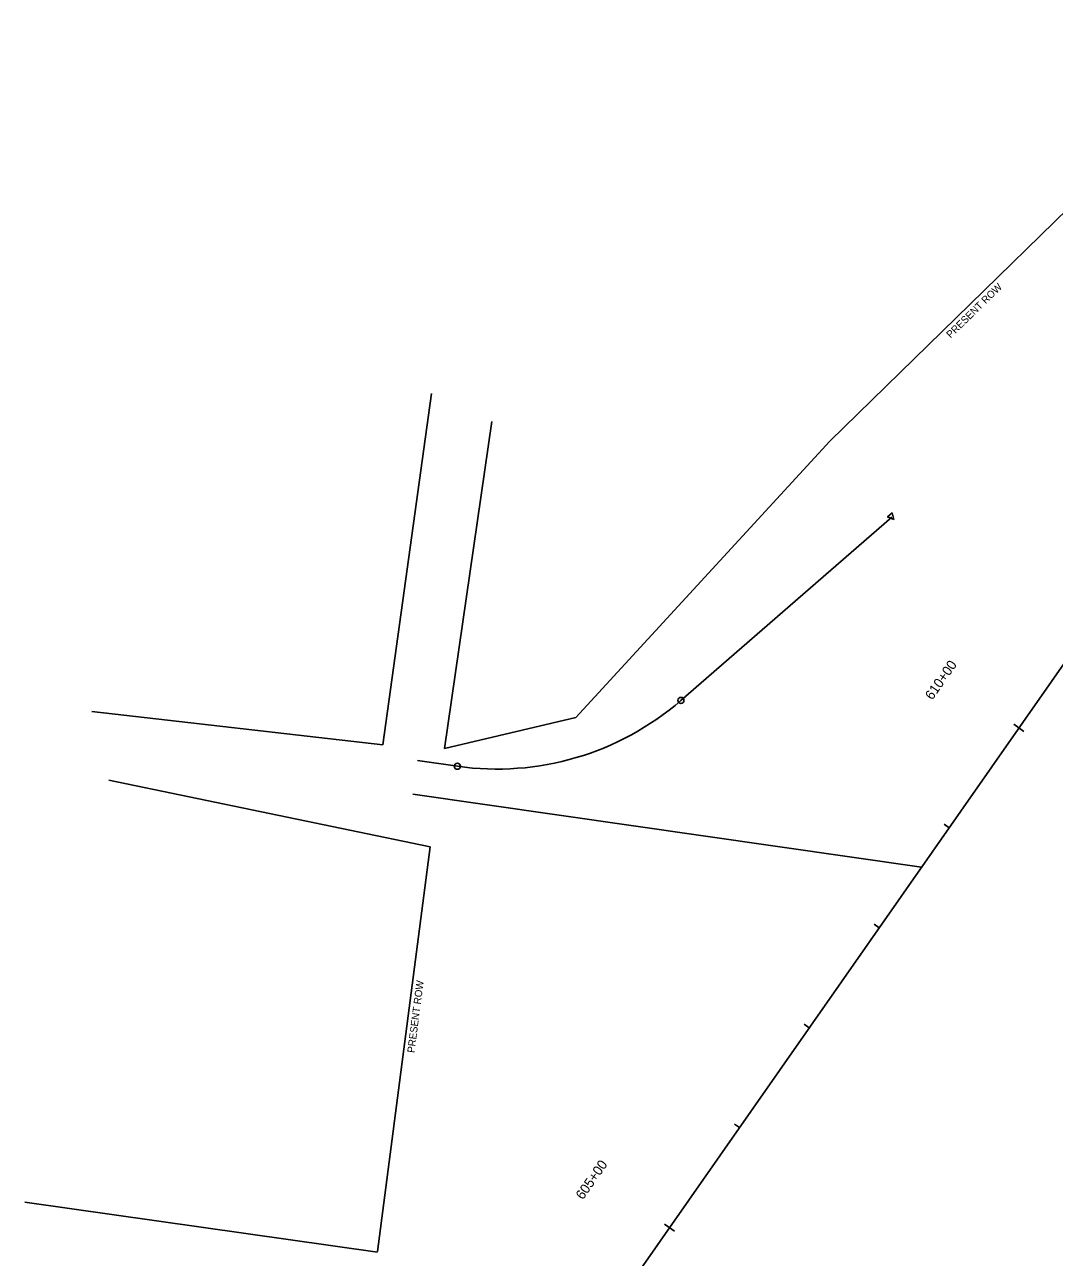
# Model space of a CAD drawing. Extents: x 1790419 to 1799551, y 243603 to 252255.
# Drawn here: x 1795876 to 1796721, y 244227 to 245238 of the extents above; entities that cross this region are included whole.
import ezdxf

# ---------------------------------------------------------------- set-up
doc = ezdxf.new("R2010")
doc.units = 0
for name, color, linetype in [('CL-CNST', 7, 'Continuous'), ('CL-CNSTTXT', 7, 'Continuous'), ('Default', 7, 'Continuous'), ('Prop_Horiz Alignment', 7, 'Continuous'), ('PRP_ROW', 7, 'Continuous'), ('PRPROWTXT', 7, 'Continuous'), ('Survey BL', 7, 'Continuous')]:
    doc.layers.add(name, color=color, linetype=linetype)

msp = doc.modelspace()

# ---------------------------------------------------------------- linework, layer by layer
at = {"layer": 'CL-CNST'}
for points in [[(1796687.6, 244664.5), (1796695.8, 244658.7)], [(1796630.3, 244582.5), (1796634.4, 244579.6)], [(1796572.9, 244500.6), (1796577, 244497.7)], [(1796515.6, 244418.6), (1796519.7, 244415.7)], [(1796458.3, 244336.7), (1796462.4, 244333.8)], [(1796401, 244254.7), (1796409.2, 244249)]]:
    msp.add_lwpolyline(points, dxfattribs=at)
at = {"layer": 'Default'}
for p, q in [((1796003.6, 243677.7), (1796959.7, 245044.8)), ((1796587.5, 244834.3), (1796414.4, 244684.1))]:
    msp.add_line(p, q, dxfattribs=at)
msp.add_arc((1796263.6, 244857.8), 230, 261.8684, 310.9519, dxfattribs=at)
at = {"layer": 'Prop_Horiz Alignment'}
msp.add_lwpolyline([(1796589.1, 244832.4), (1796583.9, 244834.6), (1796587.7, 244837.8)], close=True, dxfattribs=at)
for centre in [(1796414.4, 244684.1), (1796231.1, 244630.1)]:
    msp.add_circle(centre, 2.5, dxfattribs=at)
at = {"layer": 'PRP_ROW'}
for p, q in [((1796536.7, 244896.7), (1796886.4, 245238.3)), ((1796169.9, 244647.7), (1796209.8, 244935.8)), ((1796220.4, 244644.8), (1796259.2, 244912.8)), ((1796328.1, 244670.2), (1796536.7, 244896.7)), ((1796169.9, 244647.7), (1795931.3, 244674.9)), ((1796220.4, 244644.8), (1796328.1, 244670.2)), ((1796169.9, 244647.7), (1796169.9, 244647.7)), ((1795945.1, 244618.7), (1796208.7, 244564.1)), ((1796165.6, 244232.2), (1796208.7, 244564.1)), ((1796165.5, 244231.7), (1795876.1, 244272.6))]:
    msp.add_line(p, q, dxfattribs=at)
at = {"layer": 'Survey BL'}
for p, q in [((1796003.6, 243677.7), (1796959.7, 245044.8)), ((1796414.4, 244684.1), (1796587.5, 244834.3)), ((1796198.4, 244634.8), (1796231.1, 244630.1)), ((1796611.8, 244547.4), (1796194.5, 244607.1))]:
    msp.add_line(p, q, dxfattribs=at)
msp.add_arc((1796263.6, 244857.8), 230, 261.8684, 310.9519, dxfattribs=at)

# ---------------------------------------------------------------- texts
at = {"layer": 'CL-CNSTTXT'}
for s, p in [('610+00', (1796620.6, 244683.9)), ('605+00', (1796334, 244274.1))]:
    msp.add_text(s, height=8, rotation=55.0347, dxfattribs=at).set_placement(p)
at = {"layer": 'PRPROWTXT'}
for rotation, p in [(44.3239, (1796635.7, 244980.8)), (82.5936, (1796195.8, 244394.8))]:
    msp.add_text('PRESENT ROW', height=6, rotation=rotation, dxfattribs=at).set_placement(p)

doc.saveas('drawing.dxf')
